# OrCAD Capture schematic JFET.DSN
size A
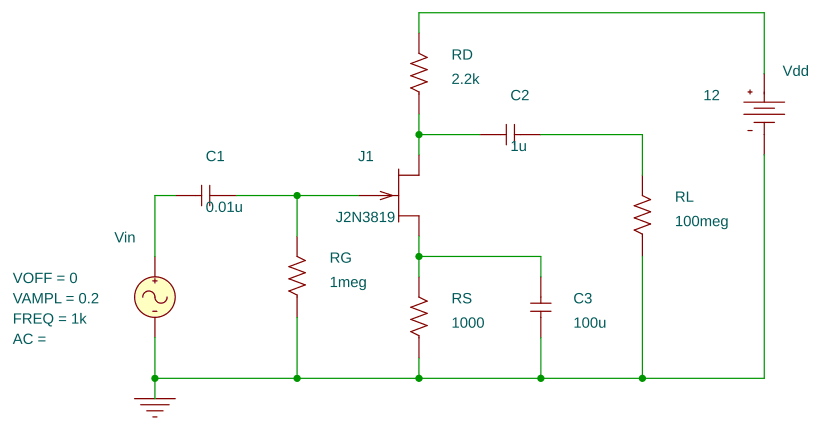
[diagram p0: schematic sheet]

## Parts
C1  0.01u  [RAD/CK05]
C2  1u  [RAD/CK05]
C3  100u  [RAD/CK05]
J1  J2N3819  [TO92]
RD  2.2k  [AX/RC05]
RG  1meg  [AX/RC05]
RL  100meg  [AX/RC05]
RS  1000  [AX/RC05]
Vdd  VDC
Vin  VSIN

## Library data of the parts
C1-C3 = C
J1 = J2N3819
RD RG RL RS = R
Vdd = VDC: DC: 12
Vin = VSIN: FREQ: 1k; VAMPL: 0.2; VOFF: 0

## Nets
0: C3.1 RG.1 RL.1 RS.1 Vdd.1(-) Vin.2(-)
N00222: C2.1 J1.1(d) RD.1
N00236: C2.2 RL.2
N00263: C1.2 J1.2(g) RG.2
N00287: C3.2 J1.3(s) RS.2
N00506: RD.2 Vdd.0(+)
N00533: C1.1 Vin.1(+)
